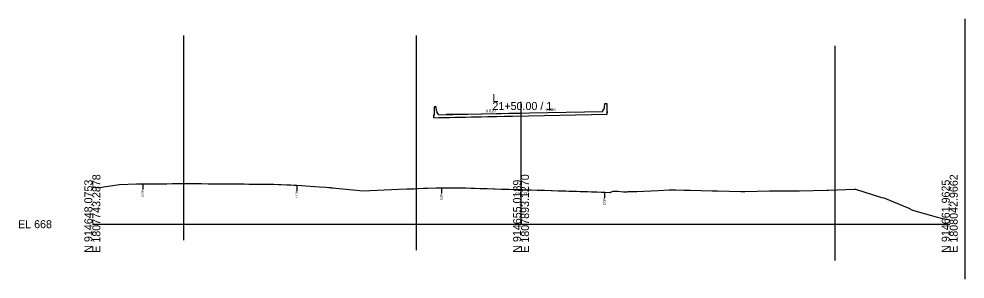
# Model space of a CAD drawing. Extents: x -26 to 1352, y -510 to 9596.
# Drawn here: x -25.7 to 305.4, y 7480.8 to 7572 of the extents above; entities that cross this region are included whole.
import ezdxf

# ---------------------------------------------------------------- set-up
doc = ezdxf.new("R2010")
doc.units = 0
for name, color, linetype in [('Default', 7, 'Continuous'), ('Exist Cross Section Cell', 7, 'Continuous'), ('Exist XS Center Line Elevation Label', 7, 'Continuous'), ('Exist XS Ground Line', 7, 'Continuous'), ('Old_Level_10', 7, 'Continuous'), ('Prop XS Bridge', 7, 'Continuous'), ('Prop XS Exc Vertical Line 1', 7, 'Continuous'), ('Prop XS Exc Vertical Line 2', 7, 'Continuous'), ('Prop XS Exc Vertical Line 3', 7, 'Continuous'), ('Prop XS Exc Vertical Line 4', 7, 'Continuous'), ('Prop XS SE Text', 7, 'Continuous')]:
    doc.layers.add(name, color=color, linetype=linetype)

msp = doc.modelspace()

# ---------------------------------------------------------------- linework, layer by layer
at = {"layer": 'Default'}
for p, q in [((179.2, 7540.86), (179.35, 7542.25)), ((179.35, 7542.25), (179.39, 7542.28)), ((179.39, 7542.28), (180.02, 7542.28)), ((180.02, 7542.28), (180.05, 7542.25)), ((180.05, 7542.25), (180.05, 7539.5)), ((119.63, 7541.13), (119.59, 7541.1)), ((119.59, 7541.1), (119.59, 7538.35)), ((120.26, 7541.13), (119.63, 7541.13)), ((120.29, 7541.1), (120.26, 7541.13)), ((120.44, 7539.71), (120.29, 7541.1)), ((121.07, 7538.61), (120.59, 7539.3)), ((121.07, 7538.35), (146.57, 7538.86)), ((121.07, 7538.35), (121.07, 7538.61)), ((150, 7538.93), (145.71, 7538.85)), ((146.57, 7538.86), (178.57, 7539.5)), ((178.57, 7539.76), (179.05, 7540.45)), ((178.57, 7539.5), (178.57, 7539.76)), ((180.05, 7539.5), (180.11, 7539.5)), ((180.11, 7539.5), (180.18, 7539.44)), ((180.18, 7539.44), (180.18, 7538.98)), ((180.18, 7538.53), (180.18, 7539.44)), ((119.46, 7537.32), (180.18, 7538.53)), ((119.53, 7538.35), (119.46, 7538.29)), ((119.46, 7537.32), (119.46, 7538.29)), ((119.46, 7538.29), (119.46, 7537.83)), ((119.59, 7538.35), (119.53, 7538.35)), ((121.09, 7537.35), (149.82, 7537.93))]:
    msp.add_line(p, q, dxfattribs=at)
for centre, start, end in [((121.3, 7539.8), 186.0111, 214.9913), ((178.34, 7540.95), 325.0087, 353.9889)]:
    msp.add_arc(centre, 0.869, start, end, dxfattribs=at)
at = {"layer": 'Exist Cross Section Cell'}
for p, q in [((150, 7500), (150, 7542.83)), ((0, 7500), (150, 7500)), ((150, 7500), (300, 7500))]:
    msp.add_line(p, q, dxfattribs=at)
at = {"layer": 'Exist XS Ground Line'}
msp.add_lwpolyline([(0, 7513.24), (1.3, 7512.94), (1.95, 7512.81), (2.36, 7512.87), (9.53, 7513.88), (15.43, 7514.1), (17.63, 7514.18), (18, 7514.18), (19.77, 7514.18), (20.57, 7514.19), (21.32, 7514.19), (23.06, 7514.2), (25.01, 7514.2), (25.54, 7514.2), (26.03, 7514.2), (28.06, 7514.21), (28.52, 7514.22), (30.57, 7514.23), (30.83, 7514.24), (32.15, 7514.28), (32.76, 7514.27), (33.07, 7514.26), (35.54, 7514.24), (35.56, 7514.24), (35.58, 7514.24), (36.19, 7514.24), (38.08, 7514.23), (38.15, 7514.23), (40.56, 7514.2), (42.78, 7514.18), (43.08, 7514.18), (43.41, 7514.17), (45.57, 7514.15), (48.39, 7514.12), (48.4, 7514.12), (48.41, 7514.12), (49.62, 7514.12), (50.58, 7514.12), (52.37, 7514.1), (53.09, 7514.1), (54.74, 7514.08), (55.6, 7514.08), (57.14, 7514.06), (58.08, 7514.05), (59.13, 7514.04), (60.57, 7514.02), (61.75, 7514), (63.09, 7513.99), (63.45, 7513.99), (65.15, 7513.97), (65.57, 7513.94), (66.12, 7513.92), (68.11, 7513.81), (69.42, 7513.77), (70.61, 7513.72), (71.03, 7513.7), (71.5, 7513.69), (79.44, 7513.1), (81.82, 7512.92), (82.8, 7512.85), (83.33, 7512.81), (83.66, 7512.78), (83.89, 7512.77), (84.06, 7512.75), (84.18, 7512.75), (85.15, 7512.67), (92.48, 7511.91), (94.68, 7511.69), (102.12, 7512.03), (107.19, 7512.28), (109.99, 7512.37), (110.31, 7512.38), (110.72, 7512.39), (111.24, 7512.41), (111.73, 7512.43), (112.6, 7512.45), (113.86, 7512.49), (115.87, 7512.57), (117.29, 7512.61), (120.3, 7512.72), (122.14, 7512.79), (123.15, 7512.78), (124.75, 7512.76), (125.68, 7512.75), (127.08, 7512.76), (127.98, 7512.76), (128.09, 7512.76), (128.35, 7512.76), (128.93, 7512.75), (130.67, 7512.7), (132.6, 7512.64), (133.17, 7512.62), (133.67, 7512.61), (135.69, 7512.55), (136.11, 7512.54), (138.18, 7512.49), (140.49, 7512.41), (140.67, 7512.4), (140.85, 7512.4), (143.16, 7512.32), (143.48, 7512.31), (145.02, 7512.26), (145.5, 7512.25), (145.71, 7512.24), (148.11, 7512.17), (148.23, 7512.17), (150, 7512.12), (150.45, 7512.11), (150.7, 7512.1), (150.98, 7512.09), (153.16, 7512.03), (153.58, 7512.02), (155.7, 7511.96), (157.61, 7511.9), (158.18, 7511.88), (160.52, 7511.81), (160.75, 7511.8), (160.95, 7511.79), (162.95, 7511.74), (163.25, 7511.73), (164.8, 7511.68), (165.7, 7511.66), (166.7, 7511.63), (168.19, 7511.58), (169.37, 7511.55), (170.73, 7511.5), (171.96, 7511.46), (173.22, 7511.41), (174.61, 7511.37), (175.74, 7511.33), (176.53, 7511.3), (178.02, 7511.25), (179.18, 7511.19), (179.37, 7511.18), (181.22, 7511.08), (181.6, 7511.29), (182.19, 7511.56), (182.2, 7511.56), (183.89, 7511.56), (185.9, 7511.33), (186.59, 7511.36), (186.67, 7511.37), (187.15, 7511.4), (187.52, 7511.41), (190.5, 7511.49), (198.03, 7511.86), (201.84, 7512.06), (202.13, 7512.05), (204.16, 7512), (206.93, 7511.97), (209.18, 7511.87), (216.94, 7511.66), (218.75, 7511.67), (226.96, 7511.46), (228.31, 7511.44), (236.97, 7511.66), (237.88, 7511.65), (246.98, 7511.65), (247.45, 7511.66), (256.99, 7511.9), (257.02, 7511.9), (257.6, 7511.92), (266.58, 7512.22), (267, 7512.23), (276.15, 7509.37), (277.01, 7509.21), (285.72, 7505.58), (287.02, 7504.91), (295.28, 7502.63), (297.03, 7502.15), (300, 7501.48)], dxfattribs=at)
at = {"layer": 'Old_Level_10'}
for p, q in [((17.63, 7514.18), (17.63, 7512.13)), ((71.5, 7513.69), (71.5, 7511.63)), ((122.14, 7512.79), (122.14, 7510.74)), ((179.18, 7511.19), (179.18, 7509.14))]:
    msp.add_line(p, q, dxfattribs=at)
at = {"layer": 'Prop XS Bridge'}
for q in [(150, 7538.93), (123.75, 7538.41)]:
    msp.add_line((129.25, 7538.52), q, dxfattribs=at)
at = {"layer": 'Prop XS Exc Vertical Line 1'}
msp.add_line((31.98, 7494.44), (31.98, 7566.09), dxfattribs=at)
at = {"layer": 'Prop XS Exc Vertical Line 2'}
msp.add_line((113.48, 7490.91), (113.48, 7566.15), dxfattribs=at)
at = {"layer": 'Prop XS Exc Vertical Line 3'}
msp.add_line((259.9, 7487.27), (259.9, 7562.51), dxfattribs=at)
at = {"layer": 'Prop XS Exc Vertical Line 4'}
msp.add_line((305.38, 7480.76), (305.38, 7571.95), dxfattribs=at)

# ---------------------------------------------------------------- texts
at = {"layer": 'Exist Cross Section Cell'}
for s, p in [('L', (140, 7542.83)), ('21+50.00 / 1', (140, 7540.03)), ('EL 668', (-26, 7498.6))]:
    msp.add_text(s, height=2.8, dxfattribs=at).set_placement(p)
for s, p in [('N 914648.0753', (0, 7490)), ('E 1807743.2878', (2.8, 7490)), ('N 914655.0189', (150, 7490)), ('E 1807893.1270', (152.8, 7490)), ('N 914661.9625', (300, 7490)), ('E 1808042.9662', (302.8, 7490))]:
    msp.add_text(s, height=2.8, rotation=90, dxfattribs=at).set_placement(p)
at = {"layer": 'Exist XS Center Line Elevation Label'}
msp.add_text('680.12', height=1, dxfattribs=at).set_placement((147.96, 7510.12))
at = {"layer": 'Old_Level_10'}
for p in [(18.02, 7509.73), (71.9, 7509.24), (122.54, 7508.34), (179.57, 7506.75)]:
    msp.add_text('EOP', height=0.787, rotation=90, dxfattribs=at).set_placement(p)
at = {"layer": 'Prop XS SE Text'}
for p in [(137.7, 7539.19), (158.63, 7539.6)]:
    msp.add_text('0.020', height=1, rotation=1.1458, dxfattribs=at).set_placement(p)

doc.saveas('drawing.dxf')
